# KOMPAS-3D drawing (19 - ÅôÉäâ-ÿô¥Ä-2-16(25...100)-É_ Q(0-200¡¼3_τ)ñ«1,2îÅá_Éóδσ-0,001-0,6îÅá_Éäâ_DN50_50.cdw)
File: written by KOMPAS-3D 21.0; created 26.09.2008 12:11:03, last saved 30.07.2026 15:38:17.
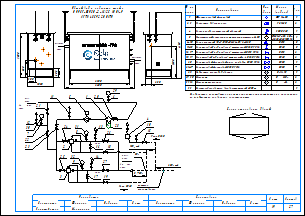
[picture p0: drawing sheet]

Sheets 1-2: A3, landscape

Document properties: Наименование: Макро:21; Автор: RaskoAdmin; Форматы листов документа: 2xA3; Полное имя файла: \\ur38nt01\Departments\КТО\КБ ПУРДГ\Заявки\Прайс-лист на типовые шкафы ГРПШ\ПУРДГ_стандарт_30_04_2026\ПУРДГ с РДГ(Н, В)\ПУРДГ-ШУЭО-2-16(25...100)-Р_ Q(0-200нм3_ч)до1,2МПа_Рвых-0,001-0,6МПа_РДГ_DN50_50.cdw

Title block, sheet 1: Наименование: Пункт учета газа / ПУГ-Ш-400-Р / ЛГТИ.485922.001ТУ; designation: ЛГТИ.03.4411141; sheet number: 1; Количество листов документа: 2; organisation: ООО "ЭЛЬСТЕР Газэлектроника"; Форматы листов документа: A3; stored path: C:\Рабочие документы\Компас\ПУГ\Схема.cdw; Разработал: Устинов; Проверил: Кошкин; Утвердил: Кошкин
Title block, sheet 2: sheet number: 2; stored path: D:\Рабочие документы\Заявки\ПУРДГ\ПУРДГ-ШУЭО-2-100-Р 4411220.cdw; designation, second copy: ЛГТИ.03.4411141-

Views: Вид 1, Вид 2
Referenced files: wcvoit.frw
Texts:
  Normal
  № на
  схеме
  Усл.
  обозн.
  Марка
  (модель)
  Кол.
  Фильтр газовый фланцевый
  ФГ 16-50
  Регулятор давления газа
  РДГ-50
  Клапан предохранительный сбросной
  КПС DN20
  Измерительный комплекс с ротационным счетчиком Ду50
  СГ-ЭК-Р-(0,2...2,0)-
  Кран кнопочный VE-РАСКО-НЗ-1,6-G1/2-М20
  DN15
  Кран шаровой "под приварку" штуцерный DN20 PN16
  DN20
  Кран шаровой "под приварку" штуцерный DN15 PN16
  Кран шаровой "под приварку" штуцерный п/п DN20 PN16
  Кран шаровой фланцевый с мех. приводом DN50 PN16
  Кран шаровой фланцевый DN50 PN16
  DN50
  Индикатор перепада давления
  Манометр
  Манометр-напоромер
  Электрообогреватель взрывозащищенный 400Вт
  Delta 15
  0...     МПа
  0...     кПа
  Общий вид и габариты шкафа
  ПУРДГ-ШУЭО-2-16(25...100)-Р
  Выход газа
  Вход газа
  logo-rasko-ge.png
  DN 1
  местное
  сопротивление
  Римп DN20
  Выход
  газа
  Р=     кПа
  Вход
  Р=       МПа
  PDI
  Схема открывания дверей
  Предприятие изготовитель может заменять комплектующие на аналогичные,
  не ухудшающие заявленных характеристик.
  Должность
  Конструктор
  Фамилия
  Подпись
  Дата
  Согласовано
  Максимкин
  Лист
  Листов
  POLYLINE_STYLE_0.18_RGB_0_0_0
  POLYLINE_STYLE_0.50_RGB_0_0_0
  POLYLINE_STYLE_0.34_RGB_0_0_0
  PHANTOM_RGB_0_0_0_SC_1_THICK_0.18
  K5LT_THIN_RGB_0_0_0_THICK_0.18
  K5LT32769_RGB_0_0_0_THICK_0.18
  K5LT12_RGB_0_0_0_SC_1_THICK_0.18
  K5LT_DASHED_RGB_0_0_0_SC_1_THICK_0.18
  ACISOTGL_RGB_0_0_0_SC_0.8_THICK_0.25
  CONTINUOUS_RGB_0_127_31_THICK_0.3
  CONTINUOUS_RGB_0_0_255_THICK_0.35
  CONTINUOUS_RGB_255_0_0_THICK_0.35
  POLYLINE_STYLE_0.25_RGB_0_0_0
  CONTINUOUS_RGB_0_0_0_THICK_0.5
  POLYLINE_STYLE_0.35_RGB_0_0_255
  CONTINUOUS_RGB_0_0_0_THICK_0.4
  CONTINUOUS_RGB_0_0_0_THICK_0.35
  НЕВИДИМАЯ_RGB_0_0_0_SC_0.3_THICK_0.25
  СONTINUOUS_RGB_0_0_0_THICK_0.25
  ОСЕВАЯ2_RGB_248_153_30_SC_0.3_THICK_0.25
  Без оформления
Dimensions and other numbers on the sheet: 1; 2, 3; 2; 4; 5; 6-10; 11-15; 16, 17; 18, 19; 20; 21-27; 7; 28; 29, 30; 31, 32; 33; 1500; 250; 300; 1050; 550; 305; 2300; 4130; 2000; 2600; 5,,,7DN 1; 30; 12; 21; 22; 23; 11; 6; 29; 24; 31; 8; 16; 13; 26; 18; 10; 15; 25; 32; 9; 3; 17; 14; 27; 19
